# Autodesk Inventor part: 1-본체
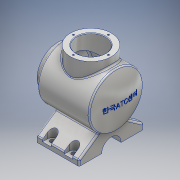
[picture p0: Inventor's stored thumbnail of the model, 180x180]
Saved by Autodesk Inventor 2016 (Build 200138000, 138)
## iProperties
Created: 2017-04
Part Number: 1-본체
Material: 알루미늄 6061
Document SubType Name: Modeling
Designer: CAMTIC
Density: 2.7 g/cm^3
Appearance: 알루미늄 - 평지
Mass: 1664.47 g
Surface Area: 1066.89 cm^2
Volume: 616.469 cm^3
Author: CAMTIC
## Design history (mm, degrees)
sketch "스케치1"
  geometry: 1 further point
sketch "스케치2"
  geometry: L1 (62, 0)-(-58, 0); L2 (62, 0)-(62, 38); L3 (62, 38)-(50, 38); L4 (50, 38)-(50, 50); L5 (50, 50)-(-46.336, 50); A1 r 113 centre (55, 0) between (-46.336, 50) and (-58, 0); 1 further point
  constraints: 10 end point, 3 perpendicular, 2 point on circle, 2 point on line, 1 centre point, 1 horizontal, 1 vertical
  dimensions: "d0" = 108 distance from line of L1.end L4; "d1" = 12 distance of L2.end L3.end; "d2" = 113 radius of A1; "d3" = 76 diameter of L3 L1; "d4" = 100 diameter of L5 L1; "d5" = 50 distance from line of point (0, 0) L4
revolve "회전1" sketch "스케치2" stored, may be unused: angle "d6" = 90 deg
sketch "스케치3"
  geometry: L1 (-60, -72)-(-60, -82); L2 (-60, -82)-(60, -82); L3 (60, -82)-(60, -72); L4 (60, -72)-(21.584, -45.101); L5 (-60, -72)-(-21.584, -45.101); L6 (0, -123.1)-(0, 78.85) reference; A1 r 50 centre (0, 0) between (21.584, -45.101) and (-21.584, -45.101) reference; 2 further points
  constraints: 10 end point, 2 perpendicular, 2 point on circle, 1 midpoint, 1 parallel, 1 vertical, 1 vertical alignment, 1 other
  dimensions: "d9" = 120 distance of L1.end L2.end; "d10" = 10 distance of L2.end L3.end; "d11" = 55 deg angle of L3 L4; "d13" = 82 distance from line of L2 point (0, 0)
extrude "돌출1" join sketch "스케치3" distance "d14" = 38; taper "d15" = 0 deg; dims "d113" = 42, "d114" = 0
node "작업 평면1"
sketch "스케치4"
  geometry: C1 r 38 at (0, 0); 1 further point
  constraints: 1 centre point, 1 coincident
  dimensions: "d17" = 76 diameter of C1
extrude "돌출2" join sketch "스케치4" stored distance "d18" = 80; taper "d19" = 0 deg
sketch "스케치6"
  geometry: L1 (20, 10)-(60, 10); L2 (60, 10)-(60, 110); L3 (60, 110)-(20, 110); L4 (20, 110)-(20, 10); L5 (20, 10)-(60, 110); L6 (60, 10)-(20, 110); L7 (0, 0)-(0, 120) reference; L8 (80, 0)-(0, 0) reference; L9 (80, 120)-(80, 0) reference; L10 (80, 120)-(0, 120) reference; 4 further points
  constraints: 12 end point, 4 midpoint, 2 parallel, 1 horizontal, 1 horizontal alignment, 1 perpendicular, 1 vertical alignment
  dimensions: "d24" = 100 distance of L1.end L2.end; "d25" = 40 distance of L2.end L3.end
  node "투영된 루프1"
hole "구멍1" sketch "스케치6" diameter "d26" = 8; stored, may be unused: countersink angle "d30" = 90 deg, drill point angle "d32" = 118 deg; dims "d27" = 6, "d28" = 6, "d29" = 2, "d31" = 8
sketch "스케치5"
  geometry: L1 (82, 60)-(82, -60) reference; L2 (82, -18)-(82, 18); A1 r 18 centre (82, 0) between (82, -18) and (82, 18); 1 further point
  constraints: 2 end point, 2 point on circle, 2 point on line, 1 centre point, 1 midpoint
  dimensions: "d21" = 18 radius of A1
extrude "돌출3" cut sketch "스케치5" stored distance "d22" = 80; taper "d23" = 0 deg
node "작업 평면2"
sketch "스케치7" dims "d41" = 8
  geometry: L1 (68, 10)-(52, 10); L2 (52, 10)-(52, 0); L3 (52, 0)-(68, 0); L4 (68, 0)-(68, 10); L5 (80, 42)-(80, 0) reference; L6 (80, 0)-(0, 0) reference; 2 further points
  constraints: 8 end point, 2 parallel, 1 collinear, 1 horizontal, 1 horizontal alignment, 1 midpoint, 1 perpendicular, 2 other
  dimensions: "d42" = 16 distance of L2.end L3.end (derived); "d43" = 10 distance of L1.end L2.end; "d44" = 20 distance from line of point (60, 10) L5
extrude "돌출4" cut sketch "스케치7" stored distance "d45" = 80; taper "d46" = 0 deg
sketch "스케치8"
  geometry: L1 (0, 0)-(0, 32.5)
  constraints: 2 end point, 1 vertical
  dimensions: "d59" = 32.5 distance of L1.start L1.end
hole "구멍3" sketch "스케치8" at (0, 32.5) diameter "d60" = 3.242; stored, may be unused: countersink angle "d64" = 90 deg, drill point angle "d66" = 118 deg; dims "d61" = 8, "d62" = 6, "d63" = 2, "d65" = 10
sketch "스케치9"
  geometry: L1 (0, 0)-(32.5, 0)
  constraints: 2 end point, 1 horizontal
  dimensions: "d70" = 32.5 distance of L1.start L1.end
hole "구멍4" sketch "스케치9" at (32.5, 0) diameter "d71" = 3.242; stored, may be unused: countersink angle "d75" = 90 deg, drill point angle "d77" = 118 deg; dims "d72" = 8, "d73" = 6, "d74" = 2, "d76" = 10
node "작업 평면3"
sketch "스케치10"
  geometry: 2 further points
  constraints: 1 coincident, 1 other
feature "엠보싱1" sketch "스케치10" dims "d0" = 108, "d1" = 12, "d2" = 113, "d3" = 76, "d4" = 100, "d5" = 50, "d16" = 65, "d82" = 0.5, "d83" = 0
sketch "스케치11"
  geometry: 1 further point
sketch "스케치12"
  geometry: L1 (62, 0)-(-48, 0); L2 (62, 0)-(62, 27); L3 (62, 27)-(40, 27); L4 (40, 27)-(40, 40); L5 (40, 40)-(-39.916, 40); L6 (62, -38)-(62, 38) reference; A1 r 103 centre (55, 0) between (-39.916, 40) and (-48, 0); 1 further point
  constraints: 10 end point, 3 perpendicular, 2 point on circle, 2 point on line, 1 centre point, 1 horizontal, 1 midpoint, 1 vertical
  dimensions: "d84" = 103 radius of A1; "d85" = 22 distance of L2.end L3.end; "d86" = 54 diameter of L3 L1; "d87" = 80 diameter of L5 L1; "d89" = 110 distance of L1.start L1.end
revolve "회전2" sketch "스케치12" stored, may be unused: angle "d90" = 90 deg
hole "구멍5" diameter "d93" = 54; stored, may be unused: countersink angle "d97" = 90 deg, drill point angle "d99" = 0 deg; dims "d91" = 10, "d92" = 10, "d94" = 8, "d95" = 6, "d96" = 2, "d98" = 10
chamfer "모따기1" distance "d106" = 1; stored, may be unused: second distance "d107" = 2, angle "d108" = 45 deg
fillet "모깎기1" dims "d109" = 3
fillet "모깎기2" dims "d110" = 3
fillet "모깎기3" dims "d111" = 3
fillet "모깎기4" dims "d112" = 3
node "솔리드1"
pattern_linear "직사각형 패턴1" dims "d35" = 100 (= d24)
pattern_linear "직사각형 패턴2" dims "d49" = 40 (= d25)
mirror "대칭1"
pattern_circular "원형 패턴3" dims angle "d101" = 360 deg
pattern_circular "원형 패턴4" dims angle "d104" = 360 deg
other parameters: "d39" = -6, "d81" = 90.25
